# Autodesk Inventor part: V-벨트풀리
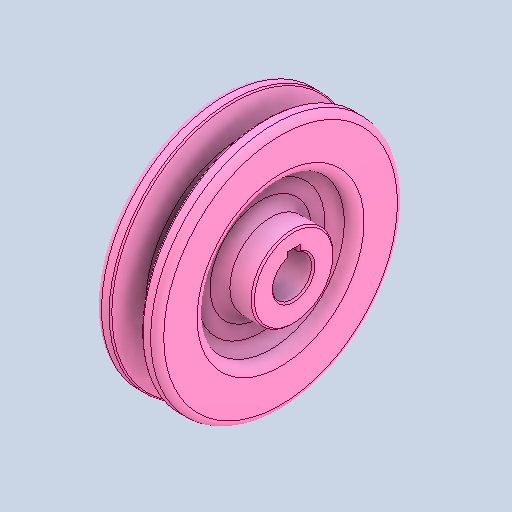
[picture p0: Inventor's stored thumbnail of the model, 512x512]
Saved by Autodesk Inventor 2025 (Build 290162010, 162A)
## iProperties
Created: 2024-07
Part Number: V-벨트풀리
Material: 강철, 탄소
Document SubType Name: Modeling
Designer: 학생
Density: 7.87 g/cm^3
Appearance: 기본값
Author: jhkim
Sending System: Autodesk Inventor 2025
Preprocessor: ST-DEVELOPER v20
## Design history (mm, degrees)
feature "솔리드1"
node "솔리드2"
